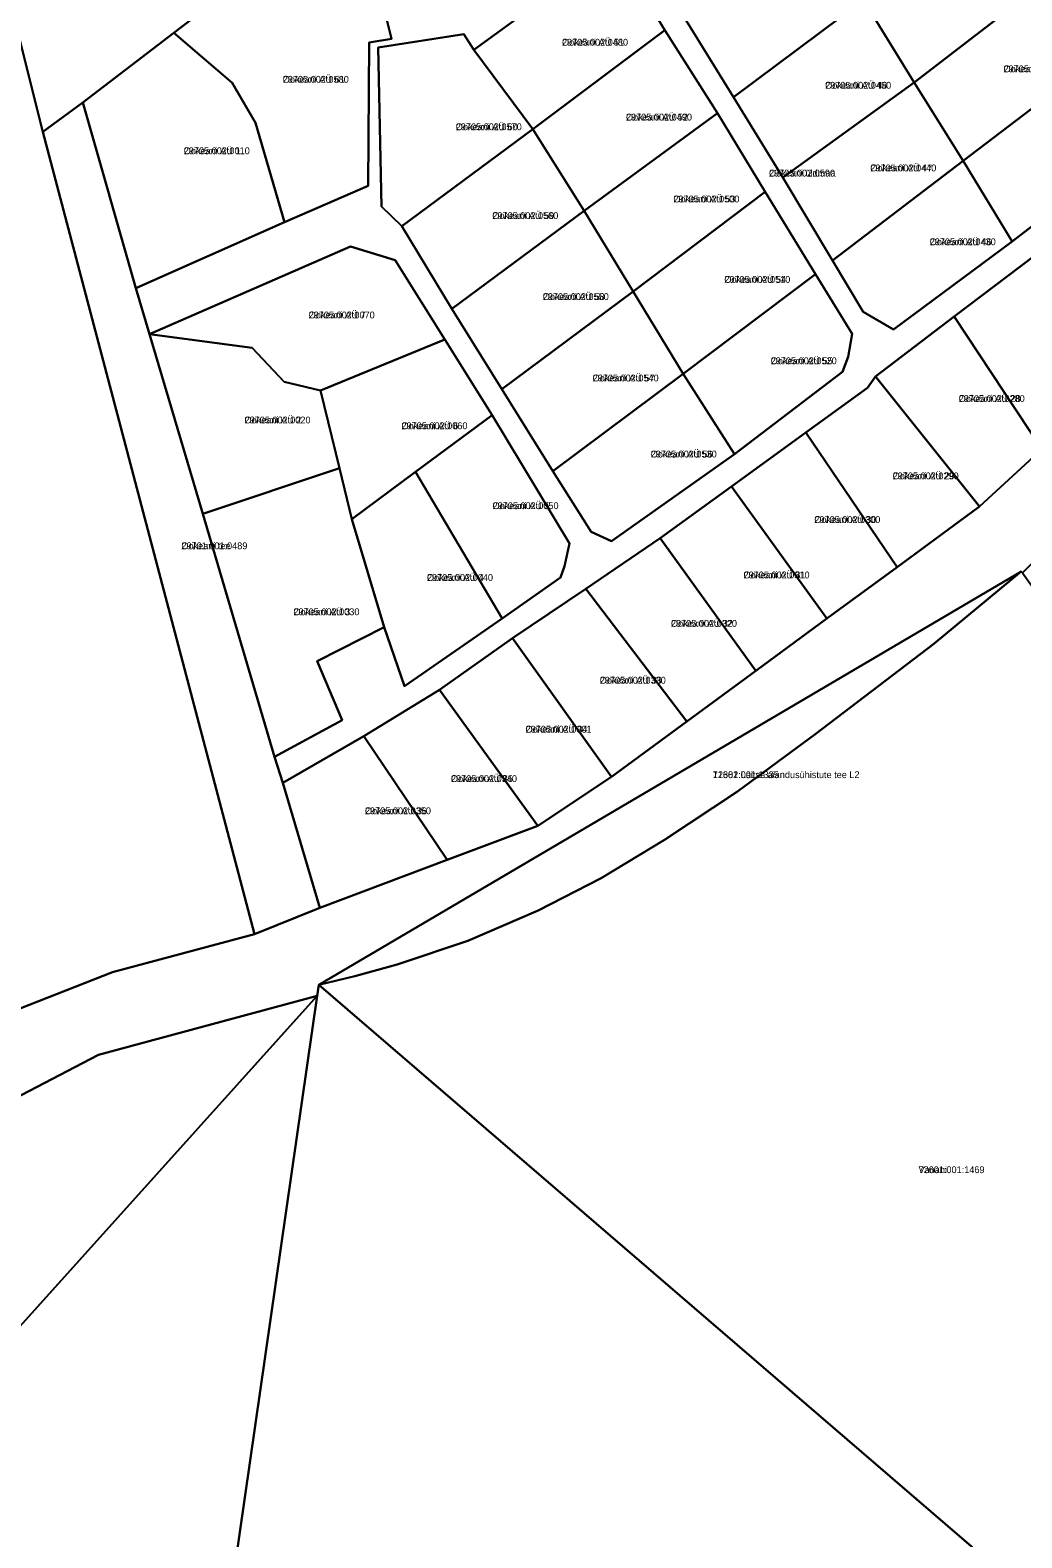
# Model space of a CAD drawing. Extents: x 504287 to 537970, y 6539941 to 6586214.
# Drawn here: x 518614.1 to 518831.9, y 6562862.8 to 6563193.8 of the extents above; entities that cross this region are included whole.
import ezdxf

# ---------------------------------------------------------------- set-up
doc = ezdxf.new("R2010")
doc.units = 0
for name, color, linetype in [('L_AADRESS', 7, 'Continuous'), ('PIIR', 7, 'Continuous'), ('TUNNUS', 7, 'Continuous')]:
    doc.layers.add(name, color=color, linetype=linetype)

msp = doc.modelspace()

# ---------------------------------------------------------------- linework, layer by layer
at = {"layer": 'PIIR'}
for points in [[(518616.88, 6563171.52), (518603.36, 6563225.02), (518725.98, 6563334.45), (518768.69, 6563286.43), (518763.38, 6563282.63), (518748.78, 6563271.92), (518732.41, 6563260.59), (518717.49, 6563248.11), (518702.62, 6563236.73), (518687.35, 6563225.04), (518685.63, 6563223.76), (518645.66, 6563193.22), (518625.63, 6563177.96)], [(518502.43, 6562916.02), (518477.37, 6562910.26), (518441, 6562902.87), (518363.7, 6562889.63), (518253.48, 6563000.68), (518403.82, 6563152.56), (518577.47, 6563328.01), (518603.36, 6563225.02), (518616.88, 6563171.52), (518663.34, 6562995.34), (518632.13, 6562986.98), (518611.67, 6562978.96), (518586.99, 6562964.59), (518544.02, 6562934.36), (518519.59, 6562922.4)], [(518807.11, 6563251.02), (518803.97, 6563253.09), (518797.82, 6563253.39), (518774.89, 6563236.9), (518749.98, 6563217.71), (518748.62, 6563211.87), (518757.55, 6563196.94), (518768.55, 6563179.13), (518779.44, 6563161.5), (518790.34, 6563143.28), (518797.06, 6563131.97), (518803.72, 6563128.09), (518829.77, 6563147.46), (518846.7, 6563160.42), (518855.04, 6563174.06), (518847.22, 6563186.59), (518836.48, 6563204.05), (518825.35, 6563221.66), (518814.27, 6563239.25)], [(518663.57, 6563173.49), (518658.44, 6563182.24), (518645.66, 6563193.22), (518685.63, 6563223.76), (518693.44, 6563191.96), (518688.52, 6563191.14), (518688.29, 6563159.66), (518669.97, 6563151.67)], [(518797.12, 6563200.46), (518825.35, 6563221.66), (518836.48, 6563204.05), (518808.29, 6563182.37)], [(518757.55, 6563196.94), (518786.24, 6563218.31), (518797.12, 6563200.46), (518768.55, 6563179.13)], [(518745.32, 6563207.17), (518741.95, 6563208.16), (518737.98, 6563208.79), (518711.56, 6563189.49), (518709.32, 6563192.92), (518690.5, 6563189.99), (518691.27, 6563155.1), (518695.71, 6563150.82), (518706.7, 6563132.64), (518717.65, 6563115), (518728.86, 6563096.96), (518737.28, 6563083.64), (518741.8, 6563081.64), (518768.81, 6563100.69), (518792.5, 6563118.83), (518793.77, 6563122.11), (518794.63, 6563127.13), (518786.56, 6563140.27), (518775.49, 6563158.34), (518765.04, 6563175.58), (518753.46, 6563193.83)], [(518711.56, 6563189.49), (518737.98, 6563208.79), (518741.95, 6563208.16), (518745.32, 6563207.17), (518753.46, 6563193.83), (518724.51, 6563172.08)], [(518808.29, 6563182.37), (518836.48, 6563204.05), (518847.22, 6563186.59), (518818.99, 6563165.13)], [(518768.55, 6563179.13), (518797.12, 6563200.46), (518808.29, 6563182.37), (518779.44, 6563161.5)], [(518625.63, 6563177.96), (518645.66, 6563193.22), (518658.44, 6563182.24), (518663.57, 6563173.49), (518669.97, 6563151.67), (518637.28, 6563137.15)], [(518691.27, 6563155.1), (518690.5, 6563189.99), (518709.32, 6563192.92), (518711.56, 6563189.49), (518724.51, 6563172.08), (518695.71, 6563150.82)], [(518724.51, 6563172.08), (518753.46, 6563193.83), (518765.04, 6563175.58), (518735.76, 6563154.14)], [(518818.99, 6563165.13), (518847.22, 6563186.59), (518855.04, 6563174.06), (518846.7, 6563160.42), (518829.77, 6563147.46)], [(518779.44, 6563161.5), (518808.29, 6563182.37), (518818.99, 6563165.13), (518790.34, 6563143.28)], [(518663.34, 6562995.34), (518616.88, 6563171.52), (518625.63, 6563177.96), (518637.28, 6563137.15), (518640.27, 6563127.06), (518651.99, 6563087.6), (518667.77, 6563034.23), (518669.54, 6563028.53), (518677.68, 6563001.14)], [(518735.76, 6563154.14), (518765.04, 6563175.58), (518775.49, 6563158.34), (518746.56, 6563136.44)], [(518695.71, 6563150.82), (518724.51, 6563172.08), (518735.76, 6563154.14), (518706.7, 6563132.64)], [(518797.06, 6563131.97), (518790.34, 6563143.28), (518818.99, 6563165.13), (518829.77, 6563147.46), (518803.72, 6563128.09)], [(518746.56, 6563136.44), (518775.49, 6563158.34), (518786.56, 6563140.27), (518757.53, 6563118.36)], [(518706.7, 6563132.64), (518735.76, 6563154.14), (518746.56, 6563136.44), (518717.65, 6563115)], [(518669.86, 6563116.58), (518662.8, 6563124.09), (518640.27, 6563127.06), (518684.45, 6563146.36), (518694.27, 6563143.33), (518705.14, 6563125.94), (518677.86, 6563114.71)], [(518834.73, 6563144.37), (518852.61, 6563117.07), (518836.29, 6563101.82), (518817.02, 6563130.98)], [(518757.53, 6563118.36), (518786.56, 6563140.27), (518794.63, 6563127.13), (518793.77, 6563122.11), (518792.5, 6563118.83), (518768.81, 6563100.69)], [(518717.65, 6563115), (518746.56, 6563136.44), (518757.53, 6563118.36), (518728.86, 6563096.96)], [(518817.02, 6563130.98), (518836.29, 6563101.82), (518822.61, 6563089.21), (518799.78, 6563117.79)], [(518640.27, 6563127.06), (518662.8, 6563124.09), (518669.86, 6563116.58), (518677.86, 6563114.71), (518682.03, 6563097.62), (518651.99, 6563087.6)], [(518682.03, 6563097.62), (518677.86, 6563114.71), (518705.14, 6563125.94), (518715.52, 6563109.32), (518698.72, 6563096.85), (518684.72, 6563086.47)], [(518737.28, 6563083.64), (518728.86, 6563096.96), (518757.53, 6563118.36), (518768.81, 6563100.69), (518741.8, 6563081.64)], [(518797.97, 6563115.28), (518799.78, 6563117.79), (518822.61, 6563089.21), (518804.49, 6563075.91), (518784.45, 6563105.52)], [(518715.52, 6563109.32), (518732.56, 6563081.09), (518731.43, 6563076.12), (518730.53, 6563073.66), (518717.75, 6563064.62), (518698.72, 6563096.85)], [(518784.45, 6563105.52), (518804.49, 6563075.91), (518789.1, 6563064.61), (518768.15, 6563093.61)], [(518651.99, 6563087.6), (518682.03, 6563097.62), (518684.72, 6563086.47), (518691.8, 6563062.73), (518677.11, 6563055.28), (518682.59, 6563042.29), (518667.77, 6563034.23)], [(518691.8, 6563062.73), (518684.72, 6563086.47), (518698.72, 6563096.85), (518717.75, 6563064.62), (518696.27, 6563049.76)], [(518768.15, 6563093.61), (518789.1, 6563064.61), (518773.5, 6563053.13), (518752.44, 6563082.31)], [(518752.44, 6563082.31), (518773.5, 6563053.13), (518758.34, 6563042.04), (518736.16, 6563071.15)], [(518831.79, 6563074.96), (518812.54, 6563059.11), (518786.69, 6563039.37), (518769.43, 6563026.65), (518753.43, 6563016.02), (518739.48, 6563007.59), (518725.69, 6563000.55), (518710.21, 6562993.84), (518694.68, 6562988.69), (518685.4, 6562986.09), (518677.48, 6562984.21)], [(518879.11, 6562810.73), (518677.48, 6562984.21), (518685.4, 6562986.09), (518694.68, 6562988.69), (518710.21, 6562993.84), (518725.69, 6563000.55), (518739.48, 6563007.59), (518753.43, 6563016.02), (518769.43, 6563026.65), (518786.69, 6563039.37), (518812.54, 6563059.11), (518831.79, 6563074.96), (518832.03, 6563074.64), (518839.93, 6563063.56), (518852.52, 6563043.72), (518866.3, 6563023.86), (518880.55, 6563003.6), (518893.41, 6562984.73), (518896.66, 6562979.21)], [(518736.16, 6563071.15), (518758.34, 6563042.04), (518741.78, 6563029.88), (518720.03, 6563060.29)], [(518720.03, 6563060.29), (518741.78, 6563029.88), (518725.61, 6563019.13), (518704.01, 6563048.94)], [(518687.39, 6563038.78), (518704.01, 6563048.94), (518725.61, 6563019.13), (518705.68, 6563011.65)], [(518669.54, 6563028.53), (518687.39, 6563038.78), (518705.68, 6563011.65), (518677.68, 6563001.14)], [(518677.1, 6562981.81), (518677.48, 6562984.21), (518879.11, 6562810.73), (518875.22, 6562663.77), (518826.94, 6562587.62), (518635.19, 6562690.91)], [(518192.21, 6562772.85), (518299.2, 6562844.83), (518335.75, 6562864.17), (518524.87, 6562904.83), (518548.12, 6562922.38), (518595.06, 6562951.11), (518629.07, 6562968.84), (518677.1, 6562981.81), (518475.75, 6562758.01), (518316.62, 6562566.33), (518257.69, 6562495.23), (518180.58, 6562562.85), (518185.96, 6562586.26), (518193.16, 6562612.47), (518199.36, 6562635.04), (518211.28, 6562678.43), (518215.15, 6562692.48), (518221.29, 6562714.82), (518225.23, 6562729.16), (518211.71, 6562770.85)], [(518475.75, 6562758.01), (518677.1, 6562981.81), (518635.19, 6562690.91), (518826.94, 6562587.62), (518766.99, 6562334.8), (518609.92, 6562245.71), (518524.03, 6562342.9), (518469.95, 6562404.01), (518435.56, 6562442.92), (518449.9, 6562487.21), (518389.7, 6562505.8), (518316.62, 6562566.33)]]:
    msp.add_lwpolyline(points, close=True, dxfattribs=at)
for points in [[(518611.67, 6562978.96), (518632.13, 6562986.98), (518663.34, 6562995.34), (518677.68, 6563001.14), (518705.68, 6563011.65), (518725.61, 6563019.13), (518741.78, 6563029.88), (518758.34, 6563042.04), (518773.5, 6563053.13), (518789.1, 6563064.61), (518804.49, 6563075.91), (518822.61, 6563089.21), (518836.29, 6563101.82), (518852.61, 6563117.07), (518862.64, 6563126.56), (518870.35, 6563136.94), (518884.98, 6563156.75), (518898.02, 6563174.23), (518911.68, 6563192.64), (518931.09, 6563218.79), (519024.68, 6563327.68)], [(519016.55, 6563293.33), (519001.41, 6563278.34), (518931.33, 6563188.8), (518926.48, 6563178.44), (518916.6, 6563165.06), (518907.12, 6563152.83), (518897.31, 6563142.07), (518885.87, 6563129.49), (518873.2, 6563116.1), (518857.32, 6563100.31), (518841.67, 6563084.19), (518832.03, 6563074.64), (518831.79, 6563074.96), (518677.48, 6562984.21), (518677.1, 6562981.81), (518629.07, 6562968.84), (518595.06, 6562951.11)], [(518834.73, 6563144.37), (518817.02, 6563130.98), (518799.78, 6563117.79), (518797.97, 6563115.28), (518784.45, 6563105.52), (518768.15, 6563093.61), (518752.44, 6563082.31), (518736.16, 6563071.15), (518720.03, 6563060.29), (518704.01, 6563048.94), (518687.39, 6563038.78), (518669.54, 6563028.53), (518667.77, 6563034.23), (518682.59, 6563042.29), (518677.11, 6563055.28), (518691.8, 6563062.73), (518696.27, 6563049.76), (518717.75, 6563064.62), (518730.53, 6563073.66), (518731.43, 6563076.12), (518732.56, 6563081.09), (518715.52, 6563109.32), (518705.14, 6563125.94), (518694.27, 6563143.33), (518684.45, 6563146.36), (518640.27, 6563127.06), (518637.28, 6563137.15), (518669.97, 6563151.67), (518688.29, 6563159.66), (518688.52, 6563191.14), (518693.44, 6563191.96), (518685.63, 6563223.76)]]:
    msp.add_lwpolyline(points, dxfattribs=at)

# ---------------------------------------------------------------- texts
at = {"layer": 'L_AADRESS'}
for s, p in [('Ookeani AÜ 51', (518730.9, 6563190.43)), ('Ookeani AÜ 42', (518827.88, 6563184.59)), ('Ookeani AÜ 61', (518669.55, 6563182.29)), ('Ookeani AÜ 48', (518788.7, 6563180.98)), ('Ookeani AÜ 52', (518744.95, 6563173.99)), ('Ookeani AÜ 60', (518707.56, 6563171.87)), ('Ookeani AÜ 1', (518647.8, 6563166.6)), ('Ookeani AÜ 47', (518798.62, 6563162.83)), ('Ookeani üldmaa', (518776.37, 6563161.69)), ('Ookeani AÜ 53', (518755.36, 6563156.01)), ('Ookeani AÜ 59', (518715.58, 6563152.36)), ('Ookeani AÜ 46', (518811.67, 6563146.61)), ('Ookeani AÜ 54', (518766.55, 6563138.35)), ('Ookeani AÜ 58', (518726.67, 6563134.57)), ('Ookeani AÜ 7', (518675.25, 6563130.54)), ('Ookeani AÜ 55', (518776.74, 6563120.48)), ('Ookeani AÜ 57', (518737.62, 6563116.7)), ('Ookeani AÜ 28', (518818.04, 6563112.19)), ('Ookeani AÜ 2', (518661.15, 6563107.48)), ('Ookeani AÜ 6', (518695.63, 6563106.21)), ('Ookeani AÜ 56', (518750.38, 6563100)), ('Ookeani AÜ 29', (518803.53, 6563095.21)), ('Ookeani AÜ 5', (518715.64, 6563088.66)), ('Ookeani AÜ 30', (518786.32, 6563085.61)), ('Ookeani tee', (518647.28, 6563079.85)), ('Ookeani AÜ 31', (518770.77, 6563073.45)), ('Ookeani AÜ 4', (518701.23, 6563072.89)), ('Ookeani AÜ 3', (518671.89, 6563065.36)), ('Ookeani AÜ 32', (518754.83, 6563062.82)), ('Ookeani AÜ 33', (518739.19, 6563050.34)), ('Ookeani AÜ 34', (518722.89, 6563039.58)), ('Ookeani AÜ 35', (518706.5, 6563028.73)), ('11382 Laitse aiandusühistute tee L2', (518764.02, 6563029.59)), ('Ookeani AÜ 36', (518687.61, 6563021.66)), ('Vanani', (518809.21, 6562942.85))]:
    msp.add_text(s, height=1.5, dxfattribs=at).set_placement(p)
at = {"layer": 'TUNNUS'}
for s, p in [('29705:002:0480', (518730.9, 6563190.43)), ('29705:002:0410', (518827.88, 6563184.59)), ('29705:002:0580', (518669.55, 6563182.29)), ('29705:002:0450', (518788.7, 6563180.98)), ('29705:002:0490', (518744.95, 6563173.99)), ('29705:002:0570', (518707.56, 6563171.87)), ('29705:002:0010', (518647.8, 6563166.6)), ('29705:002:0440', (518798.62, 6563162.83)), ('29705:002:0590', (518776.37, 6563161.69)), ('29705:002:0500', (518755.36, 6563156.01)), ('29705:002:0560', (518715.58, 6563152.36)), ('29705:002:0430', (518811.67, 6563146.61)), ('29705:002:0510', (518766.55, 6563138.35)), ('29705:002:0550', (518726.67, 6563134.57)), ('29705:002:0070', (518675.25, 6563130.54)), ('29705:002:0520', (518776.74, 6563120.48)), ('29705:002:0540', (518737.62, 6563116.7)), ('29705:002:0280', (518818.04, 6563112.19)), ('29705:002:0020', (518661.15, 6563107.48)), ('29705:002:0060', (518695.63, 6563106.21)), ('29705:002:0530', (518750.38, 6563100)), ('29705:002:0290', (518803.53, 6563095.21)), ('29705:002:0050', (518715.64, 6563088.66)), ('29705:002:0300', (518786.32, 6563085.61)), ('29701:001:0489', (518647.28, 6563079.85)), ('29705:002:0310', (518770.77, 6563073.45)), ('29705:002:0040', (518701.23, 6563072.89)), ('29705:002:0030', (518671.89, 6563065.36)), ('29705:002:0320', (518754.83, 6563062.82)), ('29705:002:0330', (518739.19, 6563050.34)), ('29705:002:0001', (518722.89, 6563039.58)), ('29705:002:0340', (518706.5, 6563028.73)), ('72601:001:1335', (518764.02, 6563029.59)), ('29705:002:0350', (518687.61, 6563021.66)), ('72601:001:1469', (518809.21, 6562942.85))]:
    msp.add_text(s, height=1.5, dxfattribs=at).set_placement(p)

doc.saveas('drawing.dxf')
